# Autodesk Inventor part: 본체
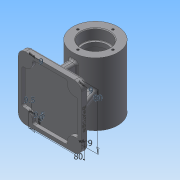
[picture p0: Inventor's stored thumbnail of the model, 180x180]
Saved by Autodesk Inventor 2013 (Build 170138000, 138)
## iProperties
Created: 2019-06
Part Number: 본체
Material: 일반
Document SubType Name: Modeling
Designer: Administrator
Density: 1 g/cm^3
Author: Administrator
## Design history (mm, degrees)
sketch "스케치1"
  geometry: L1 (32, 45)-(32, -45); L2 (32, -45)-(20, -45); L3 (20, -45)-(20, -30); L4 (20, -30)-(17, -30); L5 (17, -30)-(17, -24); L6 (17, -24)-(25, -24); L7 (25, -24)-(25, 24); L8 (25, 24)-(17, 24); L9 (17, 24)-(17, 30); L10 (17, 30)-(20, 30); L11 (20, 30)-(20, 45); L12 (20, 45)-(32, 45); L13 (0, 0)-(0, -14.682); 1 further point
  constraints: 26 end point, 6 parallel, 5 perpendicular, 1 collinear, 1 horizontal alignment, 1 midpoint, 1 vertical
  dimensions: "d0" = 90 distance of L1.start L1.end; "d2" = 64 diameter of L1 L13; "d3" = 50 diameter of L7 L13; "d4" = 40 diameter of L11 L13; "d5" = 34 diameter of L9 L13; "d6" = 15 distance between parallel lines of L10 L12; "d7" = 48 distance between parallel lines of L6 L8; "d8" = 15 distance between parallel lines of L2 L4; "d9" = 6 distance of L4.end L5.end; "d10" = 34 diameter of L5 L13; "d11" = 40 diameter of L3 L13
revolve "회전1" sketch "스케치1" stored, may be unused: angle "d12" = 90 deg
node "작업 평면1"
sketch "스케치2"
  geometry: L1 (45, 45)-(-45, 45); L2 (-45, 45)-(-45, -45); L3 (-45, -45)-(45, -45); L4 (45, -45)-(45, 45); L5 (45, 45)-(-45, -45); L6 (-45, 45)-(45, -45); 1 further point
  constraints: 12 end point, 2 midpoint, 2 parallel, 1 horizontal, 1 perpendicular
  dimensions: "d14" = 90 distance of L3.end L2.end; "d15" = 90 distance of L2.end L1.end
extrude "돌출1" join sketch "스케치2" distance "d16" = 10; taper "d17" = 0 deg
fillet "모깎기1" dims "d18" = 10
sketch "스케치3"
  geometry: L1 (5, -35)-(-5, -35); L2 (-5, -35)-(-5, 35); L3 (-5, 35)-(5, 35); L4 (5, 35)-(5, -35); L5 (5, -35)-(-5, 35); L6 (-5, -35)-(5, 35); 1 further point
  constraints: 12 end point, 2 midpoint, 2 parallel, 1 horizontal, 1 perpendicular
  dimensions: "d19" = 10 distance of L2.end L3.end; "d20" = 70 distance of L1.end L2.end
extrude "돌출2" join sketch "스케치3" stored distance "d21" = 0; taper "d22" = 0 deg
sketch "스케치4"
  geometry: L1 (-35, -55)-(-35, -65) reference; L2 (35, -55)-(-35, -55) reference; L3 (35, -65)-(35, -55) reference; L4 (35, -65)-(-35, -65) reference; L5 (-23.058, -22.189)-(-35, -55); L6 (-45, -65)-(-45, -55) reference; L7 (45, -55)-(45, -65) reference; L8 (-45, -55)-(-35, -55) reference; C1 r 20 at (0, 0) reference; 2 further points
  constraints: 2 end point, 1 point on line, 2 other
  dimensions: "d24" = 10 distance from line of L6 L5.end; "d78" = 110 deg angle of L8 L5
extrude "돌출3" join sketch "스케치4" stored distance "d28" = 10; taper "d29" = 0 deg
sketch "스케치5"
  geometry: C1 r 32 at (0, 0) reference; 1 further point
  constraints: 1 vertical alignment
  dimensions: "d30" = 25 distance of C1.centre point (0, 25)
hole "구멍1" sketch "스케치5" at (0, 25) diameter "d31" = 3.242; stored, may be unused: countersink angle "d35" = 90 deg, drill point angle "d37" = 118 deg; dims "d32" = 7, "d33" = 4, "d34" = 2, "d36" = 9
chamfer "모따기1" distance "d41" = 1; stored, may be unused: second distance "d42" = 2, angle "d43" = 45 deg
node "작업 평면2"
sketch "스케치6"
  geometry: C1 r 5 at (0, 0); 1 further point
  constraints: 1 centre point, 1 coincident
  dimensions: "d46" = 10 diameter of C1
extrude "돌출4" join sketch "스케치6" stored distance "d47" = 10; taper "d48" = 0 deg
hole "구멍2" diameter "d51" = 4.917; stored, may be unused: countersink angle "d55" = 90 deg, drill point angle "d57" = 118 deg; dims "d49" = 10, "d50" = 10, "d52" = 15, "d53" = 4, "d54" = 2, "d56" = 9
fillet "모깎기2" dims "d58" = 2, "d59" = 3, "d60" = 0.6
sketch "스케치7"
  geometry: L1 (-40, -40)-(40, -40); L2 (40, -40)-(40, 40); L3 (40, 40)-(-40, 40); L4 (-40, 40)-(-40, -40); L5 (-40, -40)-(40, 40); L6 (40, -40)-(-40, 40); 1 further point
  constraints: 12 end point, 2 midpoint, 2 parallel, 1 horizontal, 1 perpendicular
  dimensions: "d61" = 80 distance of L3.end L2.end; "d62" = 80 distance of L2.end L1.end
extrude "돌출5" cut sketch "스케치7" distance "d63" = 5; taper "d64" = 0 deg
sketch "스케치8"
  geometry: C1 r 10 at (-35, 35); C2 r 10 at (35, 35); C3 r 10 at (35, -35); C4 r 10 at (-35, -35); A1 r 10 centre (-35, 35) between (-35, 45) and (-45, 35) reference; A2 r 10 centre (35, 35) between (45, 35) and (35, 45) reference; A3 r 10 centre (35, -35) between (35, -45) and (45, -35) reference; A4 r 10 centre (-35, -35) between (-45, -35) and (-35, -45) reference; 1 further point
  constraints: 4 centre point, 4 coincident
  dimensions: "d65" = 20 diameter of C1; "d66" = 20 diameter of C2; "d67" = 20 diameter of C3; "d68" = 20 diameter of C4
extrude "돌출6" join sketch "스케치8" stored distance "d69" = 0; taper "d70" = 0 deg
fillet "모깎기3" dims "d71" = 3
sketch "스케치10"
  geometry: L1 (0, 0)-(70, 0) reference; L2 (-10, 7)-(-10, 0) reference; 2 further points
  constraints: 1 other
  dimensions: "d79" = 4 distance from line of point (35, 4) L1; "d80" = 45 distance from line of point (35, 4) L2
feature "엠보싱1" sketch "스케치10" dims "d14" = 90, "d15" = 90, "d81" = 0.5, "d82" = 0
sketch "스케치12"
  geometry: L1 (-37.101, 2)-(-37.101, -2) reference; L2 (-8, 8)-(-30.716, 8) reference; L3 (-8, 32)-(-8, 8) reference; L4 (2, 38)-(-2, 38) reference; L5 (8, 8)-(8, 32) reference; L6 (30.716, 8)-(8, 8) reference; L7 (37.101, -2)-(37.101, 2) reference; L8 (8, -8)-(30.716, -8) reference; L9 (8, -32)-(8, -8) reference; L10 (-2, -38)-(2, -38) reference; L11 (-8, -8)-(-8, -32) reference; L12 (-30.716, -8)-(-8, -8) reference; L13 (35, -42)-(-35, -42) reference; L14 (42, 35)-(42, -35) reference; L15 (-35, 42)-(35, 42) reference; L16 (-42, -35)-(-42, 35) reference; L17 (-45, 35)-(-45, -35) reference; L18 (35, 45)-(-35, 45) reference; C1 r 4.5 at (-35.5, 35.5); C2 r 4.5 at (35.5, 35.5); C3 r 4.5 at (35.5, -35.5); C4 r 4.5 at (-35.5, -35.5); A1 r 6 centre (-2, 32) between (-2, 38) and (-8, 32) reference; A2 r 6 centre (2, 32) between (8, 32) and (2, 38) reference; A3 r 6 centre (2, -32) between (2, -38) and (8, -32) reference; A4 r 6 centre (-2, -32) between (-8, -32) and (-2, -38) reference; A5 r 7 centre (-35, -35) between (-42, -35) and (-35, -42) reference; A6 r 7 centre (35, -35) between (35, -42) and (42, -35) reference; A7 r 7 centre (35, 35) between (42, 35) and (35, 42) reference; A8 r 7 centre (-35, 35) between (-35, 42) and (-42, 35) reference; 5 further points; 4 other entities
  constraints: 4 centre point, 2 horizontal alignment, 2 vertical alignment, 4 other
  dimensions: "d95" = 9 diameter of C1; "d96" = 9 diameter of C2; "d97" = 9 diameter of C3; "d98" = 9 diameter of C4; "d99" = 9.5 distance from line of L17 C1.centre; "d100" = 9.5 distance from line of C1.centre L18; "d101" = 80 dimension on C2 C1; "d102" = 80 dimension on C3 C2
node "솔리드1"
mirror "대칭1"
pattern_circular "원형 패턴1" dims angle "d39" = 360 deg
mirror "대칭2"
node "투영된 루프1"
node "투영된 루프2"
other parameters: "d13" = -65
